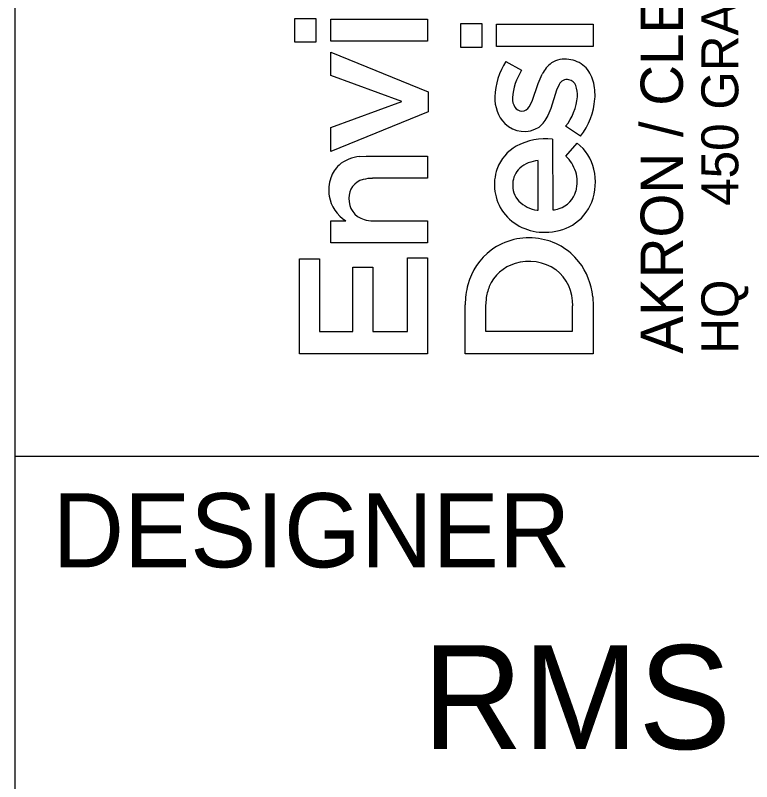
# Model space of a CAD drawing. Extents: x 117359.7 to 117393.7, y 12355.1 to 12408.1.
# Drawn here: x 117391.708 to 117392.701, y 12388.123 to 12389.157 of the extents above; entities that cross this region are included whole.
import ezdxf

# ---------------------------------------------------------------- set-up
doc = ezdxf.new("R2010")
doc.units = 0
doc.layers.add('SH_Border', color=7, linetype='Continuous')
doc.layers.add('SH_Data', color=7, linetype='Continuous')

msp = doc.modelspace()

# ---------------------------------------------------------------- linework, layer by layer
at = {"layer": 'SH_Border'}
for p, q in [((117391.7084, 12386.5625), (117391.7084, 12407.5625)), ((117391.7084, 12388.5625), (117393.2084, 12388.5625))]:
    msp.add_line(p, q, dxfattribs=at)
at = {"layer": 'SH_Data'}
for p, q in [((117392.0855, 12389.1207), (117392.0855, 12389.1527)), ((117392.0855, 12389.1527), (117392.1138, 12389.1527)), ((117392.1138, 12389.1527), (117392.1138, 12389.1207)), ((117392.1338, 12389.1219), (117392.1338, 12389.1518)), ((117392.1338, 12389.1518), (117392.2641, 12389.1518)), ((117392.2641, 12389.1518), (117392.2641, 12389.1219)), ((117392.3089, 12389.1136), (117392.3089, 12389.1457)), ((117392.3089, 12389.1457), (117392.3373, 12389.1457)), ((117392.3373, 12389.1457), (117392.3373, 12389.1136)), ((117392.3573, 12389.1148), (117392.3573, 12389.1447)), ((117392.3573, 12389.1447), (117392.4876, 12389.1447)), ((117392.4876, 12389.1447), (117392.4876, 12389.1148)), ((117392.2641, 12389.1219), (117392.1338, 12389.1219)), ((117392.1138, 12389.1207), (117392.0855, 12389.1207)), ((117392.3373, 12389.1136), (117392.3089, 12389.1136)), ((117392.4876, 12389.1148), (117392.3573, 12389.1148)), ((117392.1338, 12389.0757), (117392.1338, 12389.1071)), ((117392.1338, 12389.1071), (117392.2651, 12389.0538)), ((117392.3699, 12389.0945), (117392.3911, 12389.0827)), ((117392.2296, 12389.0405), (117392.1338, 12389.0757)), ((117392.4132, 12389.0651), (117392.4188, 12389.0777)), ((117392.4052, 12389.0412), (117392.4132, 12389.0651)), ((117392.4418, 12389.0635), (117392.4383, 12389.0558)), ((117392.2651, 12389.0538), (117392.2651, 12389.0269)), ((117392.4383, 12389.0558), (117392.4305, 12389.0313)), ((117392.1338, 12389.0054), (117392.2296, 12389.0405)), ((117392.4014, 12389.0336), (117392.4052, 12389.0412)), ((117392.4305, 12389.0313), (117392.4266, 12389.0217)), ((117392.2651, 12389.0269), (117392.1338, 12388.9733)), ((117392.1338, 12388.9733), (117392.1338, 12389.0054)), ((117392.4705, 12388.9939), (117392.4504, 12389.0072)), ((117392.4329, 12388.9899), (117392.433, 12388.8944)), ((117392.4507, 12388.9671), (117392.4661, 12388.9845)), ((117392.1728, 12388.9665), (117392.1813, 12388.9669)), ((117392.1813, 12388.9669), (117392.2641, 12388.9669)), ((117392.2641, 12388.9669), (117392.2641, 12388.9371)), ((117392.4133, 12388.8943), (117392.4133, 12388.9608)), ((117392.2641, 12388.9371), (117392.1898, 12388.9371)), ((117392.412, 12388.8941), (117392.4133, 12388.8943)), ((117392.1338, 12388.8499), (117392.1338, 12388.8798)), ((117392.1338, 12388.8798), (117392.1539, 12388.8798)), ((117392.1906, 12388.8798), (117392.2641, 12388.8798)), ((117392.2641, 12388.8798), (117392.2641, 12388.85)), ((117392.2641, 12388.85), (117392.1338, 12388.8499)), ((117392.0914, 12388.7004), (117392.0914, 12388.8285)), ((117392.0914, 12388.8285), (117392.1185, 12388.8285)), ((117392.1185, 12388.8285), (117392.1185, 12388.7307)), ((117392.237, 12388.7307), (117392.237, 12388.8297)), ((117392.237, 12388.8297), (117392.2641, 12388.8297)), ((117392.2641, 12388.8297), (117392.2641, 12388.7004)), ((117392.1634, 12388.7307), (117392.1634, 12388.8174)), ((117392.1634, 12388.8174), (117392.1906, 12388.8174)), ((117392.1906, 12388.8174), (117392.1906, 12388.7307)), ((117392.3431, 12388.7743), (117392.3425, 12388.7648)), ((117392.4869, 12388.7774), (117392.4876, 12388.7646)), ((117392.3148, 12388.7005), (117392.3148, 12388.7665)), ((117392.3425, 12388.7648), (117392.3425, 12388.7309)), ((117392.4599, 12388.7308), (117392.4599, 12388.7649)), ((117392.4876, 12388.7646), (117392.4876, 12388.7005)), ((117392.1185, 12388.7307), (117392.1634, 12388.7307)), ((117392.1906, 12388.7307), (117392.237, 12388.7307)), ((117392.3425, 12388.7309), (117392.4599, 12388.7308)), ((117392.2641, 12388.7004), (117392.0914, 12388.7004)), ((117392.4876, 12388.7005), (117392.3148, 12388.7005))]:
    msp.add_line(p, q, dxfattribs=at)
for points in [[(117392.0855, 12389.1207), (117392.0855, 12389.1527), (117392.1138, 12389.1527), (117392.1138, 12389.1207)], [(117392.1338, 12389.1219), (117392.1338, 12389.1518), (117392.2641, 12389.1518), (117392.2641, 12389.1219)], [(117392.3089, 12389.1136), (117392.3089, 12389.1457), (117392.3373, 12389.1457), (117392.3373, 12389.1136)], [(117392.3573, 12389.1148), (117392.3573, 12389.1447), (117392.4876, 12389.1447), (117392.4876, 12389.1148)], [(117392.1338, 12388.9733), (117392.1338, 12389.0054), (117392.2296, 12389.0405), (117392.1338, 12389.0757), (117392.1338, 12389.1071), (117392.2651, 12389.0538), (117392.2651, 12389.0269)], [(117392.0914, 12388.7004), (117392.0914, 12388.8285), (117392.1185, 12388.8285), (117392.1185, 12388.7307), (117392.1634, 12388.7307), (117392.1634, 12388.8174), (117392.1906, 12388.8174), (117392.1906, 12388.7307), (117392.237, 12388.7307), (117392.237, 12388.8297), (117392.2641, 12388.8297), (117392.2641, 12388.7004)]]:
    msp.add_lwpolyline(points, close=True, dxfattribs=at)
for points in [[(117392.3699, 12389.0945), (117392.3911, 12389.0827)], [(117392.4014, 12389.0336), (117392.4052, 12389.0412), (117392.4132, 12389.0651), (117392.4188, 12389.0777)], [(117392.4418, 12389.0635), (117392.4383, 12389.0558), (117392.4305, 12389.0313), (117392.4266, 12389.0217)], [(117392.4705, 12388.9939), (117392.4504, 12389.0072)], [(117392.4329, 12388.9899), (117392.433, 12388.8944)], [(117392.4507, 12388.9671), (117392.4661, 12388.9845)], [(117392.1728, 12388.9665), (117392.1813, 12388.9669), (117392.2641, 12388.9669), (117392.2641, 12388.9371), (117392.1898, 12388.9371)], [(117392.412, 12388.8941), (117392.4133, 12388.8943), (117392.4133, 12388.9608)], [(117392.1338, 12388.8499), (117392.1338, 12388.8798), (117392.1539, 12388.8798)], [(117392.1906, 12388.8798), (117392.2641, 12388.8798), (117392.2641, 12388.85), (117392.1338, 12388.8499)], [(117392.4869, 12388.7774), (117392.4876, 12388.7646), (117392.4876, 12388.7005), (117392.3148, 12388.7005)], [(117392.3431, 12388.7743), (117392.3425, 12388.7648), (117392.3425, 12388.7309), (117392.4599, 12388.7308), (117392.4599, 12388.7649)], [(117392.3148, 12388.7005), (117392.3148, 12388.7665)]]:
    msp.add_lwpolyline(points, dxfattribs=at)
for centre, radius, start, end in [((117392.4448, 12389.0451), 0.0897, 146.531, 178.7571), ((117392.4448, 12389.0451), 0.0897, 146.531, 178.7571), ((117392.455, 12389.0596), 0.0405, 125.5118, 153.4159), ((117392.455, 12389.0596), 0.0405, 125.5118, 153.4159), ((117392.449, 12389.0651), 0.0326, 80.1719, 122.5197), ((117392.449, 12389.0651), 0.0326, 80.1719, 122.5197), ((117392.4512, 12389.0607), 0.0367, 47.7934, 84.6892), ((117392.4512, 12389.0607), 0.0367, 47.7934, 84.6892), ((117392.4536, 12389.0414), 0.0749, 146.5112, 176.9101), ((117392.4536, 12389.0414), 0.0749, 146.5112, 176.9101), ((117392.4463, 12389.0571), 0.0427, 14.9966, 46.2063), ((117392.4463, 12389.0571), 0.0427, 14.9966, 46.2063), ((117392.4522, 12389.0588), 0.0114, 76.6609, 155.7053), ((117392.4522, 12389.0588), 0.0114, 76.6609, 155.7053), ((117392.4524, 12389.0576), 0.0126, 21.5098, 78.5262), ((117392.4524, 12389.0576), 0.0126, 21.5098, 78.5262), ((117392.4343, 12389.0501), 0.0321, 354.5726, 22.068), ((117392.4343, 12389.0501), 0.0321, 354.5726, 22.068), ((117392.4189, 12389.0492), 0.0712, 355.8306, 15.3914), ((117392.4189, 12389.0492), 0.0712, 355.8306, 15.3914), ((117392.4051, 12389.0449), 0.0501, 177.5366, 222.7932), ((117392.4051, 12389.0449), 0.0501, 177.5366, 222.7932), ((117392.4015, 12389.0448), 0.0228, 178.4747, 211.0868), ((117392.4015, 12389.0448), 0.0228, 178.4747, 211.0868), ((117392.3909, 12389.054), 0.0757, 321.811, 354.7969), ((117392.3909, 12389.054), 0.0757, 321.811, 354.7969), ((117392.3979, 12389.0507), 0.0922, 321.9777, 355.8738), ((117392.3979, 12389.0507), 0.0922, 321.9777, 355.8738), ((117392.3917, 12389.0392), 0.0115, 212.2368, 268.3777), ((117392.3917, 12389.0392), 0.0115, 212.2368, 268.3777), ((117392.3918, 12389.0384), 0.0107, 267.716, 333.7337), ((117392.3918, 12389.0384), 0.0107, 267.716, 333.7337), ((117392.3894, 12389.0383), 0.0408, 308.0877, 335.9874), ((117392.3894, 12389.0383), 0.0408, 308.0877, 335.9874), ((117392.3944, 12389.0378), 0.0375, 225.9854, 302.4797), ((117392.3944, 12389.0378), 0.0375, 225.9854, 302.4797), ((117392.4236, 12388.9066), 0.0838, 83.615, 118.2876), ((117392.4236, 12388.9066), 0.0838, 83.615, 118.2876), ((117392.4108, 12388.9315), 0.0558, 118.8308, 160.6244), ((117392.4108, 12388.9315), 0.0558, 118.8308, 160.6244), ((117392.4259, 12388.9342), 0.0644, 13.5336, 51.3615), ((117392.4259, 12388.9342), 0.0644, 13.5336, 51.3615), ((117392.1771, 12388.9168), 0.0499, 94.9696, 130.2225), ((117392.1771, 12388.9168), 0.0499, 94.9696, 130.2225), ((117392.4122, 12388.928), 0.0549, 19.0357, 45.4406), ((117392.4122, 12388.928), 0.0549, 19.0357, 45.4406), ((117392.4163, 12388.9186), 0.0424, 94.008, 130.8817), ((117392.4163, 12388.9186), 0.0424, 94.008, 130.8817), ((117392.1719, 12388.9251), 0.0402, 132.2219, 161.6818), ((117392.1719, 12388.9251), 0.0402, 132.2219, 161.6818), ((117392.4188, 12388.9286), 0.0644, 160.5201, 215.7831), ((117392.4188, 12388.9286), 0.0644, 160.5201, 215.7831), ((117392.4089, 12388.9288), 0.0298, 132.9851, 177.179), ((117392.4089, 12388.9288), 0.0298, 132.9851, 177.179), ((117392.4191, 12388.9322), 0.047, 344.6059, 17.007), ((117392.4191, 12388.9322), 0.047, 344.6059, 17.007), ((117392.4148, 12388.9317), 0.0758, 339.3542, 13.3785), ((117392.4148, 12388.9317), 0.0758, 339.3542, 13.3785), ((117392.1871, 12388.9207), 0.056, 162.2736, 187.7919), ((117392.1871, 12388.9207), 0.056, 162.2736, 187.7919), ((117392.1832, 12388.9111), 0.025, 103.6865, 182.2187), ((117392.1832, 12388.9111), 0.025, 103.6865, 182.2187), ((117392.1895, 12388.891), 0.046, 89.6049, 105.3284), ((117392.1895, 12388.891), 0.046, 89.6049, 105.3284), ((117392.4101, 12388.9275), 0.0311, 175.0013, 223.283), ((117392.4101, 12388.9275), 0.0311, 175.0013, 223.283), ((117392.4308, 12388.9296), 0.035, 288.0077, 343.5508), ((117392.4308, 12388.9296), 0.035, 288.0077, 343.5508), ((117392.1787, 12388.9205), 0.0476, 188.962, 238.7037), ((117392.1787, 12388.9205), 0.0476, 188.962, 238.7037), ((117392.1858, 12388.9081), 0.0276, 175.5854, 255.1439), ((117392.1858, 12388.9081), 0.0276, 175.5854, 255.1439), ((117392.4173, 12388.9361), 0.0423, 225.0619, 262.7974), ((117392.4173, 12388.9361), 0.0423, 225.0619, 262.7974), ((117392.4273, 12388.9277), 0.0626, 300.9427, 338.7323), ((117392.4273, 12388.9277), 0.0626, 300.9427, 338.7323), ((117392.4331, 12388.9146), 0.0202, 269.7003, 294.8711), ((117392.4331, 12388.9146), 0.0202, 269.7003, 294.8711), ((117392.4209, 12388.933), 0.0687, 217.7452, 271.6543), ((117392.4209, 12388.933), 0.0687, 217.7452, 271.6543), ((117392.1902, 12388.922), 0.0422, 254.0916, 270.5284), ((117392.1902, 12388.922), 0.0422, 254.0916, 270.5284), ((117392.4239, 12388.9349), 0.0706, 269.2048, 300.3341), ((117392.4239, 12388.9349), 0.0706, 269.2048, 300.3341), ((117392.4007, 12388.7704), 0.0864, 81.194, 125.9984), ((117392.4007, 12388.7704), 0.0864, 81.194, 125.9984), ((117392.403, 12388.7738), 0.0827, 37.8521, 82.402), ((117392.403, 12388.7738), 0.0827, 37.8521, 82.402), ((117392.4023, 12388.7714), 0.0865, 127.2362, 165.148), ((117392.4023, 12388.7714), 0.0865, 127.2362, 165.148), ((117392.3973, 12388.7703), 0.054, 106.1881, 157.3861), ((117392.3973, 12388.7703), 0.054, 106.1881, 157.3861), ((117392.4012, 12388.7611), 0.0639, 55.6727, 107.2093), ((117392.4012, 12388.7611), 0.0639, 55.6727, 107.2093), ((117392.3943, 12388.7681), 0.0931, 5.7333, 37.304), ((117392.3943, 12388.7681), 0.0931, 5.7333, 37.304), ((117392.4013, 12388.7675), 0.0587, 357.4662, 52.2665), ((117392.4013, 12388.7675), 0.0587, 357.4662, 52.2665), ((117392.4227, 12388.7653), 0.1078, 164.7861, 179.3704), ((117392.4227, 12388.7653), 0.1078, 164.7861, 179.3704), ((117392.4067, 12388.7664), 0.0641, 157.3571, 172.9275), ((117392.4067, 12388.7664), 0.0641, 157.3571, 172.9275)]:
    msp.add_arc(centre, radius, start, end, dxfattribs=at)

# ---------------------------------------------------------------- texts
for s, height, p in [('450 GRANT ST., AKRON, OH  44311', 0.049846, (117392.6833, 12388.8999)), ('AKRON / CLEVELAND / COLUMBUS', 0.056969, (117392.6085, 12388.7005)), ('HQ ', 0.04985, (117392.6833, 12388.7005))]:
    msp.add_text(s, height=height, rotation=90, dxfattribs=at).set_placement(p)
for s, height, p in [('DESIGNER', 0.1, (117391.7584, 12388.4125)), ('RMS', 0.14, (117392.2575, 12388.1675))]:
    msp.add_text(s, height=height, dxfattribs=at).set_placement(p)

doc.saveas('drawing.dxf')
